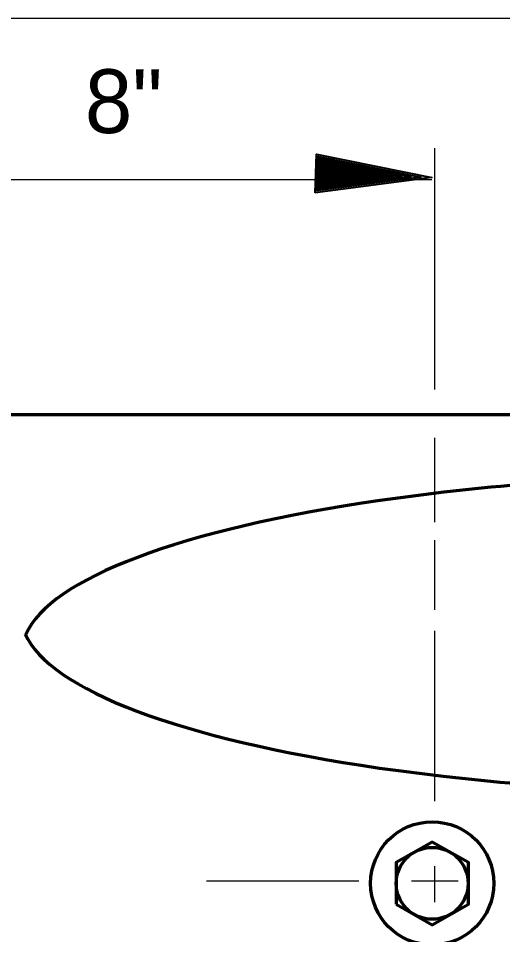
# Model space of a CAD drawing. Extents: x 895.6 to 930.4, y -2278.6 to -2254.7.
# Drawn here: x 915.738 to 916.715, y -2272.09 to -2270.241 of the extents above; entities that cross this region are included whole.
import ezdxf

# ---------------------------------------------------------------- set-up
doc = ezdxf.new("R2010")
doc.units = 0
doc.header["$LTSCALE"] = 0.051
doc.layers.add('1', color=7, linetype='Continuous', lineweight=70)
doc.layers.add('3', color=7, linetype='Continuous', lineweight=40)

msp = doc.modelspace()

# ---------------------------------------------------------------- hatches: boundary and pattern name
at = {"layer": '3'}
for points in [[(916.33692, -2270.59308), (916.33958, -2270.51508), (916.57225, -2270.562), (916.57225, -2270.562)], [(916.33817, -2270.58917), (916.3405, -2270.519), (916.54983, -2270.56117), (916.54983, -2270.56117)], [(916.33917, -2270.58567), (916.34133, -2270.52258), (916.52975, -2270.56058), (916.52975, -2270.56058)], [(916.34017, -2270.58258), (916.34208, -2270.52583), (916.51167, -2270.56), (916.51167, -2270.56)], [(916.34092, -2270.57992), (916.34275, -2270.52875), (916.49542, -2270.5595), (916.49542, -2270.5595)], [(916.34192, -2270.57725), (916.34342, -2270.53125), (916.48075, -2270.559), (916.48075, -2270.559)], [(916.3425, -2270.57492), (916.34383, -2270.5335), (916.46758, -2270.5585), (916.46758, -2270.5585)], [(916.34325, -2270.573), (916.34433, -2270.53567), (916.45558, -2270.55817), (916.45558, -2270.55817)], [(916.34358, -2270.57117), (916.34492, -2270.5375), (916.445, -2270.55767), (916.445, -2270.55767)], [(916.34425, -2270.56942), (916.34533, -2270.53908), (916.43533, -2270.55742), (916.43533, -2270.55742)], [(916.34475, -2270.56792), (916.34567, -2270.54075), (916.42667, -2270.55708), (916.42667, -2270.55708)], [(916.34508, -2270.5665), (916.346, -2270.54217), (916.41892, -2270.55675), (916.41892, -2270.55675)], [(916.34558, -2270.56542), (916.34625, -2270.54333), (916.41175, -2270.55658), (916.41175, -2270.55658)], [(916.346, -2270.56425), (916.3465, -2270.54442), (916.40567, -2270.55642), (916.40567, -2270.55642)], [(916.34625, -2270.56333), (916.34683, -2270.54542), (916.39992, -2270.55625), (916.39992, -2270.55625)], [(916.3465, -2270.56242), (916.34692, -2270.54625), (916.39483, -2270.55592), (916.39483, -2270.55592)], [(916.34675, -2270.56158), (916.34725, -2270.547), (916.39025, -2270.55575), (916.39025, -2270.55575)], [(916.34692, -2270.56083), (916.34733, -2270.54783), (916.38617, -2270.55567), (916.38617, -2270.55567)], [(916.34725, -2270.56042), (916.3475, -2270.54858), (916.3825, -2270.55567), (916.3825, -2270.55567)], [(916.34742, -2270.55983), (916.34775, -2270.54925), (916.37925, -2270.55558), (916.37925, -2270.55558)], [(916.34767, -2270.5595), (916.348, -2270.54992), (916.37625, -2270.55575), (916.37625, -2270.55575)], [(916.34767, -2270.55892), (916.348, -2270.55042), (916.3735, -2270.55558), (916.3735, -2270.55558)], [(916.34783, -2270.55842), (916.34817, -2270.55083), (916.37108, -2270.55533), (916.37108, -2270.55533)], [(916.348, -2270.55817), (916.34825, -2270.55133), (916.36892, -2270.55542), (916.36892, -2270.55542)]]:
    msp.add_hatch(color=256, dxfattribs=at).paths.add_polyline_path(points)

# ---------------------------------------------------------------- linework, layer by layer
at = {"layer": '1', "lineweight": 25}
for p, q in [((915.22142, -2270.24067), (918.1585, -2270.24067)), ((916.57792, -2270.98983), (916.57792, -2270.5025)), ((914.87908, -2270.56583), (916.57192, -2270.56583)), ((916.57792, -2271.25783), (916.57792, -2271.08733)), ((916.57792, -2271.43442), (916.57792, -2271.29442)), ((916.57792, -2271.82117), (916.57792, -2271.47708)), ((916.57792, -2272.02517), (916.57792, -2271.95208)), ((916.11742, -2271.98208), (916.42475, -2271.98208)), ((916.53125, -2271.98208), (916.62558, -2271.98208))]:
    msp.add_line(p, q, dxfattribs=at)
at = {"layer": '1'}
for p, q in [((919.14467, -2271.04083), (915.53433, -2271.04083)), ((916.59617, -2271.19733), (916.46792, -2271.21392)), ((915.75317, -2271.48433), (915.75208, -2271.48367)), ((916.46692, -2271.75408), (916.59517, -2271.77067))]:
    msp.add_line(p, q, dxfattribs=at)
msp.add_lwpolyline([(916.50033, -2272.02858), (916.57308, -2272.07083), (916.646, -2272.02858), (916.646, -2271.945), (916.57308, -2271.90367), (916.50033, -2271.945)], close=True, dxfattribs=at)
for radius in [0.12424, 0.07248]:
    msp.add_circle((916.5729, -2271.98686), radius, dxfattribs=at)
for centre, start_param, end_param in [((917.23656, -2271.52159), 4.712389, 5.1561874), ((917.23656, -2271.52159), 5.2538073, 6.1792823), ((917.23554, -2271.4464), 0.1038925, 1.0293717), ((917.23554, -2271.4464), 1.1269942, 1.5707963)]:
    msp.add_ellipse(centre, major_axis=(-1.49147, 0), ratio=0.240741, start_param=start_param, end_param=end_param, dxfattribs=at)
at = {"layer": '3'}
for points in [[(916.33692, -2270.59308), (916.33958, -2270.51508), (916.57225, -2270.562), (916.57225, -2270.562)], [(916.33817, -2270.58917), (916.3405, -2270.519), (916.54983, -2270.56117), (916.54983, -2270.56117)], [(916.33917, -2270.58567), (916.34133, -2270.52258), (916.52975, -2270.56058), (916.52975, -2270.56058)], [(916.34017, -2270.58258), (916.34208, -2270.52583), (916.51167, -2270.56), (916.51167, -2270.56)], [(916.34092, -2270.57992), (916.34275, -2270.52875), (916.49542, -2270.5595), (916.49542, -2270.5595)], [(916.34192, -2270.57725), (916.34342, -2270.53125), (916.48075, -2270.559), (916.48075, -2270.559)], [(916.3425, -2270.57492), (916.34383, -2270.5335), (916.46758, -2270.5585), (916.46758, -2270.5585)], [(916.34325, -2270.573), (916.34433, -2270.53567), (916.45558, -2270.55817), (916.45558, -2270.55817)], [(916.34358, -2270.57117), (916.34492, -2270.5375), (916.445, -2270.55767), (916.445, -2270.55767)], [(916.34425, -2270.56942), (916.34533, -2270.53908), (916.43533, -2270.55742), (916.43533, -2270.55742)], [(916.34475, -2270.56792), (916.34567, -2270.54075), (916.42667, -2270.55708), (916.42667, -2270.55708)], [(916.34508, -2270.5665), (916.346, -2270.54217), (916.41892, -2270.55675), (916.41892, -2270.55675)], [(916.34558, -2270.56542), (916.34625, -2270.54333), (916.41175, -2270.55658), (916.41175, -2270.55658)], [(916.346, -2270.56425), (916.3465, -2270.54442), (916.40567, -2270.55642), (916.40567, -2270.55642)], [(916.34625, -2270.56333), (916.34683, -2270.54542), (916.39992, -2270.55625), (916.39992, -2270.55625)], [(916.3465, -2270.56242), (916.34692, -2270.54625), (916.39483, -2270.55592), (916.39483, -2270.55592)], [(916.34675, -2270.56158), (916.34725, -2270.547), (916.39025, -2270.55575), (916.39025, -2270.55575)], [(916.34692, -2270.56083), (916.34733, -2270.54783), (916.38617, -2270.55567), (916.38617, -2270.55567)], [(916.34725, -2270.56042), (916.3475, -2270.54858), (916.3825, -2270.55567), (916.3825, -2270.55567)], [(916.34742, -2270.55983), (916.34775, -2270.54925), (916.37925, -2270.55558), (916.37925, -2270.55558)], [(916.34767, -2270.5595), (916.348, -2270.54992), (916.37625, -2270.55575), (916.37625, -2270.55575)], [(916.34767, -2270.55892), (916.348, -2270.55042), (916.3735, -2270.55558), (916.3735, -2270.55558)], [(916.34783, -2270.55842), (916.34817, -2270.55083), (916.37108, -2270.55533), (916.37108, -2270.55533)], [(916.348, -2270.55817), (916.34825, -2270.55133), (916.36892, -2270.55542), (916.36892, -2270.55542)]]:
    msp.add_lwpolyline(points, close=True, dxfattribs=at)

# ---------------------------------------------------------------- texts
at = {"layer": '1'}
msp.add_text('8"', height=0.1286, dxfattribs=at).set_placement((915.87233, -2270.47225))

doc.saveas('drawing.dxf')
